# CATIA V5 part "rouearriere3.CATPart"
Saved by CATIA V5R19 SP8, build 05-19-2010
Part number: rouearriere3
Bounding box of the stored display mesh (mm): x -150 to -130, y -6.601 to 53.399, z -58.732 to 1.268
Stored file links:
  G:\EU_thinkMotion\CFAO_2010\MMS_groupe2\MMS_groupe2\A reprendre\jcauchy\rouearriere3.CATPart
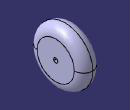
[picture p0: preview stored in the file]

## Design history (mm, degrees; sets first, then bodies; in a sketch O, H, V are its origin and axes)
Parameters
  Rayonroue_rouearriere3 = 30 mm
  Largeurroue_rouearriere = 10 mm
  Rayoncoungeroue_rouearriere3 = 10 mm
  Rayonfixation_rouearriere3 = 2.5 mm
Set1
  Plane1: stored without definition
  Plane2: stored without definition
  Sketch1 on Plane2, origin (-140, 0, 0), H (0, -1, 0), V (0, 0, 1)
    circle A1 centre (-23.3987, -28.7323) radius 30
    point P1 (-23.3987, -28.7323)
    reference projected point E1 (-23.3987, -28.7323) from Point1
    radius A1 = 30 {= Rayonroue_rouearriere3}
    distance E1 P1 = 0
  Point1: stored without definition
  Point2: stored without definition
Body1 (main body)
  Pad1: profile Sketch1, direction (-1, 0, 0), length 10 {= Largeurroue_rouearriere}, mirrored extent
  Fillet1: radius 10 {= Rayoncoungeroue_rouearriere3}, on edge [face of Pad1 from Sketch1.A1 | end face of Pad1]
  Fillet2: radius 10 {= Rayoncoungeroue_rouearriere3}, on edge [start face of Pad1 | face of Pad1 from Sketch1.A1]
  Sketch2 on end face of Pad1, origin (-150, 23.3987, -28.7323), H (0, 1, 0), V (0, 0, -1)
    point P1 (0, 0)
  Hole1: placed by Sketch2, at (-150, 23.3987, -28.7323) direction (1, 0, 0), diameter 5 {= Rayonfixation_rouearriere3 *2}, depth 20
